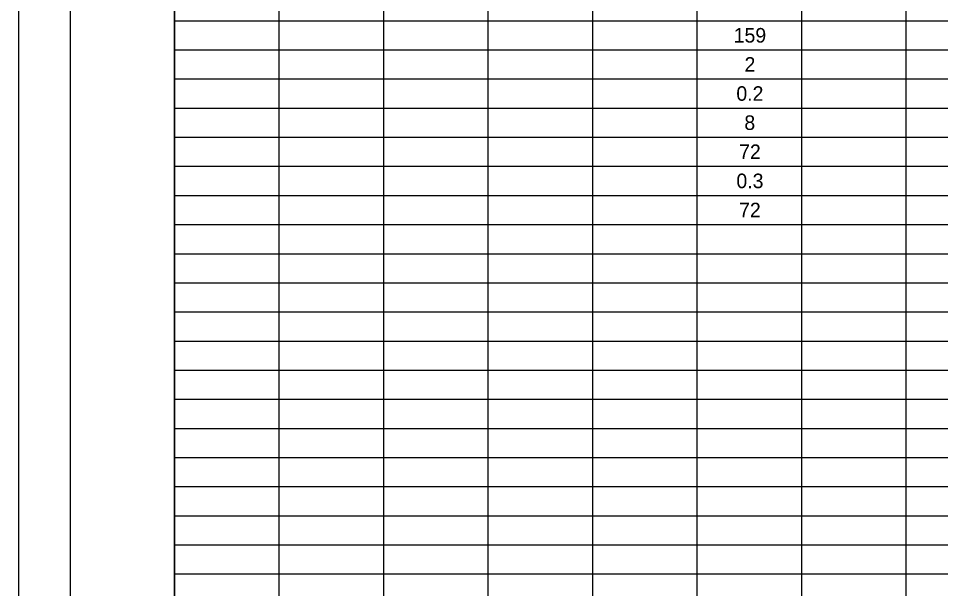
# Model space of a CAD drawing. Extents: x 0 to 34, y 0 to 22.
# Drawn here: x 0 to 8.87, y 11 to 16.48 of the extents above; entities that cross this region are included whole.
import ezdxf

# ---------------------------------------------------------------- set-up
doc = ezdxf.new("R2010")
doc.units = 0
for name, color, linetype in [('Default', 7, 'Continuous'), ('SH_Border', 7, 'Continuous'), ('SH_Cut_Line', 7, 'Continuous')]:
    doc.layers.add(name, color=color, linetype=linetype)

msp = doc.modelspace()

# ---------------------------------------------------------------- linework, layer by layer
at = {"layer": 'Default'}
for p, q in [((1.5, 21.5), (1.5, 0.5008)), ((2.5047, 20.94), (2.5047, 0.5008)), ((3.5093, 20.94), (3.5093, 0.5008)), ((4.514, 20.94), (4.514, 0.5008)), ((5.5187, 20.94), (5.5187, 0.5008)), ((6.5234, 20.94), (6.5234, 0.5008)), ((7.528, 20.94), (7.528, 0.5008)), ((8.5327, 20.94), (8.5327, 0.5008)), ((1.5, 16.4602), (32.0024, 16.4602)), ((1.5, 16.1802), (32.0024, 16.1802)), ((1.5, 15.9002), (32.0024, 15.9002)), ((1.5, 15.6202), (32.0024, 15.6202)), ((1.5, 15.3402), (32.0024, 15.3402)), ((1.5, 15.0602), (32.0024, 15.0602)), ((1.5, 14.7802), (32.0024, 14.7802)), ((1.5, 14.5002), (32.0024, 14.5002)), ((1.5, 14.2203), (32.0024, 14.2203)), ((1.5, 13.9403), (32.0024, 13.9403)), ((1.5, 13.6603), (32.0024, 13.6603)), ((1.5, 13.3803), (32.0024, 13.3803)), ((1.5, 13.1003), (32.0024, 13.1003)), ((1.5, 12.8203), (32.0024, 12.8203)), ((1.5, 12.5403), (32.0024, 12.5403)), ((1.5, 12.2603), (32.0024, 12.2603)), ((1.5, 11.9803), (32.0024, 11.9803)), ((1.5, 11.7004), (32.0024, 11.7004)), ((1.5, 11.4204), (32.0024, 11.4204)), ((1.5, 11.1404), (32.0024, 11.1404))]:
    msp.add_line(p, q, dxfattribs=at)
at = {"layer": 'SH_Border'}
for points in [[(0.5, 21.5), (1.5, 21.5), (1.5, 0.5), (0.5, 0.5)], [(1.5, 21.5), (33.5, 21.5), (33.5, 0.5), (1.5, 0.5)]]:
    msp.add_lwpolyline(points, close=True, dxfattribs=at)
at = {"layer": 'SH_Cut_Line'}
msp.add_lwpolyline([(0, 0), (34, 0), (34, 22), (0, 22)], close=True, dxfattribs=at)

# ---------------------------------------------------------------- texts
at = {"layer": 'Default'}
for s, p in [('159', (6.8768, 16.2502)), ('2', (6.9809, 15.9702)), ('0.2', (6.9025, 15.6902)), ('8', (6.9795, 15.4102)), ('72', (6.9291, 15.1302)), ('0.3', (6.903, 14.8502)), ('72', (6.9291, 14.5702))]:
    msp.add_text(s, height=0.14, dxfattribs=at).set_placement(p)

doc.saveas('drawing.dxf')
